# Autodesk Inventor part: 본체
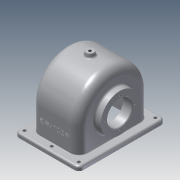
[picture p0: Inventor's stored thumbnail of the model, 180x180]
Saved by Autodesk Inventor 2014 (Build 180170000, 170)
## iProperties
Created: 2015-09
Part Number: 본체
Material: 알루미늄 6061
Document SubType Name: Modeling
Designer: sda3
Density: 2.71 g/cm^3
Appearance: 알루미늄 - 평지
Mass: 725.841 g
Surface Area: 895.545 cm^2
Volume: 267.838 cm^3
Author: sda3
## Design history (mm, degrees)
sketch "스케치2"
  geometry: L1 (52, -70)-(-52, -70); L2 (-52, -70)-(-52, 70); L3 (-52, 70)-(52, 70); L4 (52, 70)-(52, -70); L5 (-52, 70)-(52, -70); 2 further points
  constraints: 10 end point, 2 parallel, 1 coincident, 1 horizontal, 1 midpoint, 1 perpendicular
  dimensions: "d0" = 104 distance of L2.end L3.end; "d1" = 140 distance of L3.end L1.start
extrude "돌출1" new body sketch "스케치2" distance "d2" = 7; taper "d3" = 0 deg
sketch "스케치3"
  geometry: L1 (-38.5, 57)-(38.5, 57); L2 (38.5, 57)-(38.5, -57); L3 (38.5, -57)-(-38.5, -57); L4 (-38.5, -57)-(-38.5, 57); L5 (38.5, -57)-(-38.5, 57); 2 further points
  constraints: 10 end point, 2 parallel, 1 coincident, 1 horizontal, 1 midpoint, 1 perpendicular
  dimensions: "d4" = 77 distance of L2.end L3.end; "d5" = 114 distance of L3.end L1.start
extrude "돌출2" join sketch "스케치3" distance "d6" = 40; taper "d7" = 0 deg
sketch "스케치4"
  geometry: L1 (7, 57)-(7, -57) reference; L2 (7, 57)-(47, 57) reference; L3 (47, -57)-(47, 57) reference; L4 (7, -57)-(47, -57) reference; L5 (47, 57)-(47, -57); A1 r 57 centre (47, 0) between (47, -57) and (47, 57); 1 further point
  constraints: 2 end point, 2 point on circle, 1 centre point, 1 collinear
  dimensions: "d8" = 57 radius of A1
extrude "돌출3" join sketch "스케치4" stored distance "d9" = 77; taper "d10" = 0 deg
sketch "스케치5"
  geometry: L1 (-38.5, 47)-(38.5, 47) reference; L2 (38.5, 47)-(38.5, 47) reference; L3 (38.5, 47)-(-38.5, 47) reference; L4 (-38.5, 47)-(-38.5, 47) reference; L5 (-38.5, 7)-(38.5, 7) reference; L6 (-38.5, 7)-(-38.5, 47) reference; L7 (38.5, 47)-(-38.5, 47) reference; L8 (38.5, 7)-(38.5, 47) reference; L9 (-38.5, 47)-(38.5, 47); L10 (-38.5, 104)-(-38.5, 47) reference; L11 (-38.5, 104)-(38.5, 104) reference; L12 (38.5, 47)-(38.5, 104) reference; L13 (-33.5, 47)-(-33.5, 98); L14 (-33.5, 98)-(33.5, 98); L15 (33.5, 98)-(33.5, 47); 1 further point
  constraints: 8 end point, 2 perpendicular, 2 point on line, 1 collinear, 1 parallel
  dimensions: "d11" = 5 distance between parallel lines of L12 L15; "d12" = 5 distance between parallel lines of L10 L13; "d13" = 6 distance between parallel lines of L11 L14
revolve "회전1" sketch "스케치5" stored, may be unused: angle "d14" = 90 deg
sketch "스케치6"
  geometry: L1 (-33.5, 51)-(-33.5, -51) reference; L2 (33.5, 19.799)-(33.5, -19.799) reference; L3 (33.5, -19.799)-(-33.5, -19.799) reference; L4 (-33.5, -19.799)-(-33.5, 19.799) reference; L5 (-33.5, 19.799)-(33.5, 19.799) reference; L6 (-52, -70)-(52, -70) reference; L7 (52, -70)-(52, 70) reference; L8 (52, 70)-(-52, 70) reference; L9 (-52, 70)-(-52, -70) reference; L10 (33.5, 51)-(-33.5, 51) reference; L11 (33.5, 51)-(33.5, -51) reference; L12 (33.5, -51)-(-33.5, -51) reference; L13 (-33.5, 51)-(33.5, 51); L14 (33.5, 51)-(33.5, -51); L15 (33.5, -51)-(-33.5, -51); L16 (-33.5, -51)-(-33.5, 51); 1 further point
  constraints: 8 end point, 2 parallel, 1 horizontal, 1 perpendicular
extrude "돌출4" cut sketch "스케치6" distance "d15" = 47; taper "d16" = 0 deg
sketch "스케치7"
  geometry: C1 r 31 at (57, 40); A1 r 57 centre (57, 40) between (114, 40) and (0, 40) reference; 1 further point
  constraints: 1 centre point, 1 coincident
  dimensions: "d17" = 62 diameter of C1
extrude "돌출5" join sketch "스케치7" distance "d18" = 10; taper "d19" = 0 deg
sketch "스케치8"
  geometry: C1 r 31 at (0, 0) reference; 2 further points
  constraints: 1 coincident
hole "구멍1" sketch "스케치8" at (0, 0) diameter "d20" = 40; stored, may be unused: countersink angle "d24" = 90 deg, drill point angle "d26" = 118 deg; dims "d21" = 6, "d22" = 4, "d23" = 2, "d25" = 8
sketch "스케치9"
  geometry: L1 (-33.5, 47)-(33.5, 47) reference; L2 (-38.5, 104)-(-38.5, 47) reference; L3 (33.5, 47)-(-38.5, 47); L4 (-19.5, 47)-(-19.5, 75); L5 (-33.5, 98)-(-33.5, 47) reference; L6 (-19.5, 75)-(-33.5, 86.747); L7 (-38.5, 84.416)-(-33.237, 80); L8 (-33.237, 80)-(-35.5, 80); L9 (-35.5, 80)-(-35.5, 47); L10 (48.5, 16)-(48.5, 78) reference; L11 (-38.5, 84.416)-(-38.5, 47); L12 (-33.5, 86.747)-(-38.5, 84.416); 1 further point
  constraints: 16 end point, 4 perpendicular, 4 point on line, 1 collinear, 1 parallel
  dimensions: "d27" = 84 distance between parallel lines of L9 L10; "d28" = 28 distance from line of L1 L4.end; "d29" = 50 deg angle of L4 L6; "d30" = 5 distance between parallel lines of L6 L7; "d31" = 66 diameter of L8 L3; "d32" = 16 distance between parallel lines of L9 L4
revolve "회전2" stored, may be unused: angle "d33" = 90 deg
revolve "회전3" stored, may be unused: angle "d34" = 90 deg
sketch "스케치11"
  geometry: C1 r 33 at (0, 0) reference; 2 further points
  constraints: 1 coincident
hole "구멍2" sketch "스케치11" at (0, 0) diameter "d35" = 40; stored, may be unused: countersink angle "d39" = 90 deg, drill point angle "d41" = 118 deg; dims "d36" = 6, "d37" = 4, "d38" = 2, "d40" = 8
node "작업 평면1"
sketch "스케치12"
  geometry: C1 r 6 at (0, 0); 1 further point
  constraints: 1 centre point, 1 coincident
  dimensions: "d43" = 12 diameter of C1
extrude "돌출6" join sketch "스케치12" stored distance "d44" = 10; taper "d45" = 10 deg
chamfer "모따기1" distance "d46" = 1; stored, may be unused: second distance "d47" = 2, angle "d48" = 45 deg
fillet "모깎기1" dims "d49" = 7, "d50" = 9, "d51" = 14, "d52" = 3, "d53" = 0.5
sketch "스케치13"
  geometry: L1 (-44, 62)-(44, 62); L2 (44, 62)-(44, -62); L3 (44, -62)-(-44, -62); L4 (-44, -62)-(-44, 62); L5 (44, -62)-(-44, 62); 8 further points
  constraints: 10 end point, 5 coincident, 3 midpoint, 2 parallel, 1 horizontal, 1 perpendicular
  dimensions: "d54" = 124 distance of L1.end L2.end; "d55" = 88 distance of L1.start L1.end
hole "구멍3" sketch "스케치13" at (-44, 62), (44, 62), (44, -62), (-44, -62), (0, -62), (0, 62) diameter "d56" = 5; stored, may be unused: countersink angle "d60" = 90 deg, drill point angle "d62" = 118 deg; dims "d57" = 6, "d58" = 4, "d59" = 2, "d61" = 8
fillet "모깎기2" dims "d63" = 1, "d100" = 3
sketch "스케치14"
  geometry: L1 (0, 0)-(0, 24); L2 (0, 0)-(-24, 0); L3 (0, 0)-(0, -24); L4 (0, 0)-(24, 0); C1 r 31 at (0, 0) reference; C2 r 21 at (0, 0) reference; 5 further points
  constraints: 8 end point, 4 coincident, 1 vertical, 17 other
  dimensions: "d64" = 24 distance of L1.start L1.end; "d67" = 360 deg dimension on C1.centre L1.end (derived)
hole "구멍4" sketch "스케치14" at (0, 24), (-24, 0), (0, -24), (24, 0) diameter "d69" = 2.459; stored, may be unused: countersink angle "d73" = 90 deg, drill point angle "d75" = 118 deg; dims "d70" = 6, "d71" = 4, "d72" = 2, "d74" = 8
sketch "스케치15"
  geometry: L1 (0, 0)-(0, 28); C1 r 33 at (0, 0) reference; C2 r 21 at (0, 0) reference; 5 further points
  constraints: 2 end point, 1 coincident, 1 vertical, 5 other
  dimensions: "d76" = 28 distance of L1.start L1.end; "d79" = 360 deg dimension on C1.centre point (0, 28) (derived)
hole "구멍5" sketch "스케치15" at (0, 28), (-28, 0), (0, -28), (28, 0) diameter "d81" = 2.459; stored, may be unused: countersink angle "d85" = 90 deg, drill point angle "d87" = 118 deg; dims "d82" = 7, "d83" = 4, "d84" = 2, "d86" = 9
sketch "스케치16"
  geometry: C1 r 6 at (0, 0) reference; 1 further point
  constraints: 1 coincident
hole "구멍6" sketch "스케치16" at (0, 0) diameter "d88" = 4.459; stored, may be unused: countersink angle "d92" = 90 deg, drill point angle "d94" = 118 deg; dims "d89" = 7, "d90" = 4, "d91" = 2, "d93" = 9
sketch "스케치17"
  geometry: L1 (0, -39)-(0, 0) reference; L2 (24.5, -47)-(24.5, -17); L3 (-0.387, -13.398)-(49.387, -13.398); L4 (49.387, -13.398)-(49.387, -20.602); L5 (49.387, -20.602)-(-0.387, -20.602); L6 (-0.387, -20.602)-(-0.387, -13.398); L7 (-0.387, -13.398)-(49.387, -20.602)
  constraints: 4 end point, 1 horizontal, 1 midpoint, 1 parallel, 2 other
  dimensions: "d95" = 30 distance of L2.end L2.start; "d96" = 49.77477 distance of L4.end L5.end; "d97" = 7.20489 distance of L3.end L4.end
feature "엠보싱1" sketch "스케치17" dims "d0" = 104, "d1" = 140, "d8" = 57, "d98" = 0.5, "d99" = 0
node "솔리드1"
node "투영된 루프1"
node "투영된 루프2"
node "투영된 루프3"
node "투영된 루프4"
